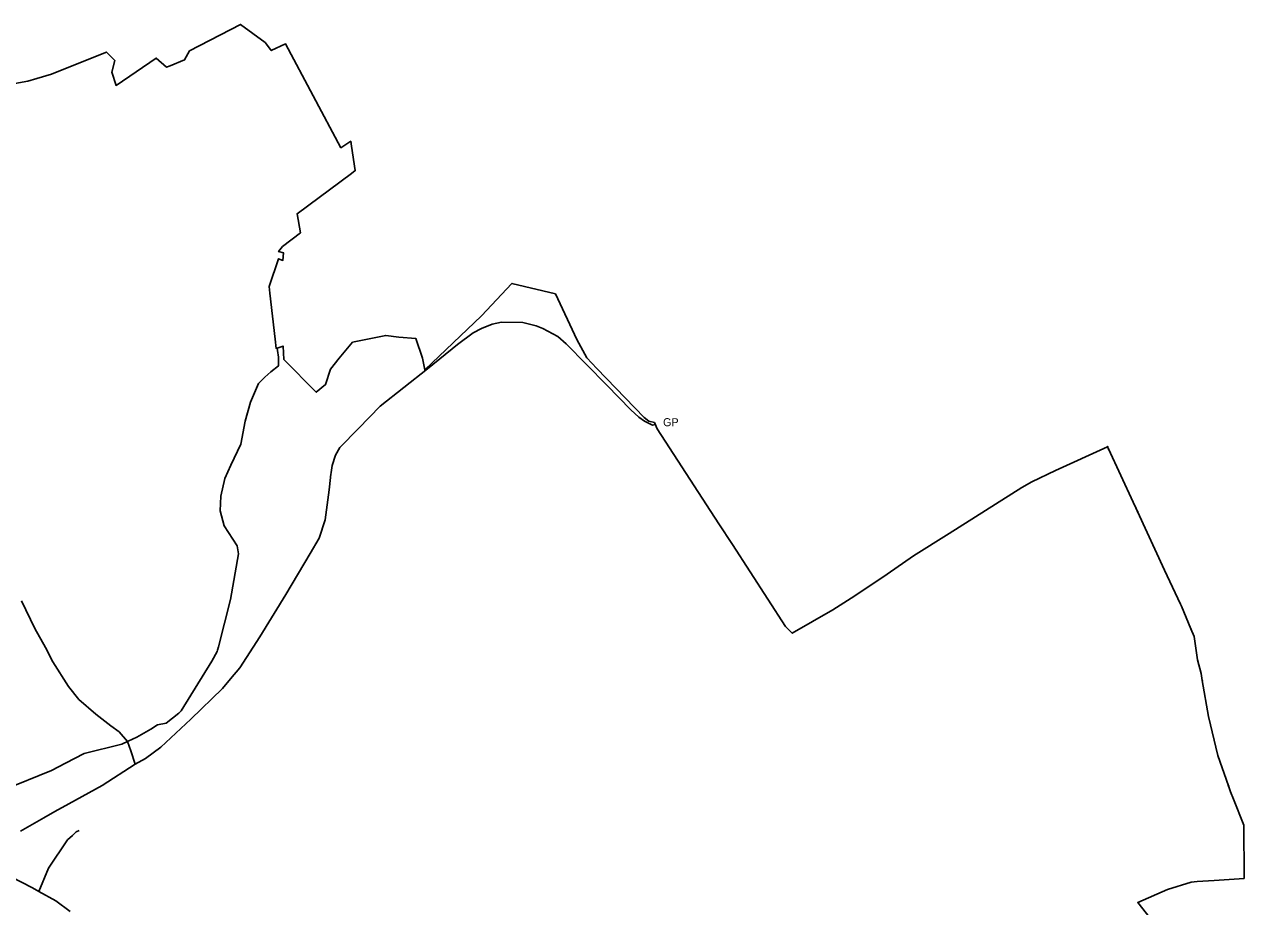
# Model space of a CAD drawing. Extents: x -617038 to -609441, y -1109294 to -1104285.
# Drawn here: x -612071 to -610546, y -1107289 to -1106187 of the extents above; entities that cross this region are included whole.
import ezdxf

# ---------------------------------------------------------------- set-up
doc = ezdxf.new("R2010")
doc.units = 0
for name, color, linetype in [('BOD_SET', 7, 'Continuous'), ('CESTY', 7, 'Continuous'), ('OVNE_PRE', 7, 'Continuous'), ('OVNE_SET', 7, 'Continuous'), ('VODA', 7, 'Continuous')]:
    doc.layers.add(name, color=color, linetype=linetype)

msp = doc.modelspace()

# ---------------------------------------------------------------- linework, layer by layer
at = {"layer": 'BOD_SET'}
for p, q in [((-610717.9, -1106714.2), (-610716.9, -1106715.2)), ((-610717.9, -1106715.2), (-610716.9, -1106714.2)), ((-610716.6, -1106717), (-610715.6, -1106718)), ((-610716.6, -1106718), (-610715.6, -1106717)), ((-610686, -1106783.4), (-610685, -1106784.4)), ((-610686, -1106784.4), (-610685, -1106783.4)), ((-610682.3, -1106791.4), (-610681.3, -1106792.4)), ((-610682.3, -1106792.4), (-610681.3, -1106791.4)), ((-610680.6, -1106795), (-610679.6, -1106796)), ((-610680.6, -1106796), (-610679.6, -1106795)), ((-610626.8, -1106910.8), (-610625.8, -1106911.8)), ((-610626.8, -1106911.8), (-610625.8, -1106910.8)), ((-610613.7, -1106941.8), (-610612.7, -1106942.8)), ((-610613.7, -1106942.8), (-610612.7, -1106941.8)), ((-610599.5, -1107006.1), (-610598.5, -1107007.1)), ((-610599.5, -1107007.1), (-610598.5, -1107006.1)), ((-610566.8, -1107138), (-610565.8, -1107139)), ((-610566.8, -1107139), (-610565.8, -1107138)), ((-610560.6, -1107154.4), (-610559.6, -1107155.4)), ((-610560.6, -1107155.4), (-610559.6, -1107154.4)), ((-610547.2, -1107251.9), (-610546.2, -1107252.9)), ((-610547.2, -1107252.9), (-610546.2, -1107251.9))]:
    msp.add_line(p, q, dxfattribs=at)
at = {"layer": 'CESTY'}
for points in [[(-612075.8, -1107195.1), (-612046.5, -1107178.3), (-612033, -1107170.5), (-612015.4, -1107161), (-611973.7, -1107138), (-611932.5, -1107111.4), (-611919.4, -1107104.3), (-611900.6, -1107089.9), (-611863.1, -1107055.1), (-611823.4, -1107016.9), (-611813.3, -1107004.8), (-611801.6, -1106990.8), (-611776.6, -1106952.3), (-611744.4, -1106899.3), (-611713.9, -1106848.3), (-611702.7, -1106829), (-611695.1, -1106805.9), (-611690, -1106768.6), (-611688.3, -1106753), (-611688.2, -1106752.3), (-611687.3, -1106744), (-611686.4, -1106738), (-611682.2, -1106725.1), (-611676.9, -1106715.6), (-611653.6, -1106692.1), (-611626.5, -1106663.9), (-611567.1, -1106617.3), (-611529.9, -1106587.2), (-611510.2, -1106572.6), (-611499.7, -1106566.9), (-611486.3, -1106561.6), (-611474.7, -1106559.3), (-611448, -1106559.6), (-611431.6, -1106563.5), (-611423.2, -1106566.9), (-611404.5, -1106577.1), (-611394, -1106586.2), (-611343, -1106637.7), (-611312.9, -1106668.6), (-611303.1, -1106677.9), (-611296.2, -1106682.8), (-611292.8, -1106684.3), (-611286, -1106687.6), (-611282.7, -1106687.1)], [(-611932.5, -1107111.4), (-611937.7, -1107094.8), (-611942, -1107082.9), (-611952.6, -1107070.8), (-611962.8, -1107063.2), (-611981.8, -1107048.8), (-612003, -1107030.4), (-612015.9, -1107014.1), (-612035.3, -1106983.5), (-612044.5, -1106965.5), (-612057.7, -1106941.7), (-612074.6, -1106907.4)]]:
    msp.add_lwpolyline(points, dxfattribs=at)
at = {"layer": 'OVNE_PRE'}
for points in [[(-610646.3, -1106868.9), (-610680.1, -1106795.5), (-610681.8, -1106791.9), (-610685.5, -1106783.9), (-610716.1, -1106717.5), (-610717.4, -1106714.8)], [(-610613, -1107258.5), (-610605.4, -1107258), (-610584.2, -1107256.6), (-610546.7, -1107254), (-610546.7, -1107252.4), (-610547, -1107187.3), (-610560.1, -1107154.9), (-610563.8, -1107145.7), (-610566.3, -1107138.5), (-610579.8, -1107100.3), (-610591.3, -1107051.8), (-610599, -1107006.6), (-610600.4, -1106998.1), (-610605.2, -1106980.9), (-610609.1, -1106951.8), (-610613.2, -1106942.3), (-610625.2, -1106913.9), (-610626.3, -1106911.3), (-610646.3, -1106868.9)], [(-610574.7, -1107411.6), (-610598.8, -1107383.5), (-610617.5, -1107361.1), (-610646.3, -1107326.4), (-610647.2, -1107325.3), (-610679.7, -1107284.3), (-610642.7, -1107268), (-610613, -1107258.5)]]:
    msp.add_lwpolyline(points, dxfattribs=at)
at = {"layer": 'OVNE_SET'}
for points in [[(-611283.7, -1106684.6), (-611290.6, -1106682.9), (-611296.4, -1106678.4), (-611355.7, -1106617.1), (-611368.1, -1106603.6), (-611380.6, -1106580.9), (-611407.4, -1106523.9), (-611461.7, -1106510.7), (-611499.7, -1106551.2), (-611570.7, -1106618.7), (-611573.4, -1106604.2), (-611581.9, -1106579.5), (-611603, -1106578), (-611619.4, -1106575.7), (-611660.7, -1106583.9), (-611677.7, -1106604), (-611688.4, -1106617.8), (-611694.8, -1106637), (-611706.3, -1106646.6), (-611746.9, -1106605.6), (-611747.6, -1106589), (-611756.4, -1106591.8), (-611757.5, -1106580.4), (-611764, -1106523), (-611765, -1106514.6), (-611753.4, -1106479.9), (-611747.8, -1106482), (-611747.1, -1106472.5), (-611753.2, -1106471), (-611748.3, -1106464.4), (-611725.9, -1106447.4), (-611730.2, -1106423.6), (-611662.2, -1106373.2), (-611657.5, -1106369.7), (-611662.1, -1106339.1), (-611663, -1106333), (-611675.3, -1106341.2), (-611744.7, -1106211.3), (-611762.5, -1106219.9), (-611764.7, -1106217), (-611770.1, -1106209.9), (-611801, -1106187.1), (-611864.7, -1106220.3), (-611870.8, -1106231.3), (-611888.8, -1106238.7), (-611893.2, -1106240.5), (-611906.2, -1106229.3), (-611956.3, -1106263.4), (-611961.7, -1106246.7), (-611957.7, -1106232.4), (-611968.3, -1106221.7), (-611996.6, -1106233.1), (-612036.9, -1106249.3), (-612055.4, -1106254.8), (-612066.7, -1106258), (-612131.6, -1106269.8)], [(-610717.4, -1106714.8), (-610782.5, -1106744.4), (-610812.1, -1106758.4), (-610824.5, -1106765.8), (-610915.2, -1106823), (-610959.7, -1106851), (-610992.7, -1106873.8), (-611033.1, -1106900.9), (-611060.5, -1106918.4), (-611111.4, -1106947.8), (-611119.7, -1106939.2), (-611186.2, -1106837), (-611203.2, -1106810.9), (-611280.3, -1106692.4), (-611283.7, -1106684.6)]]:
    msp.add_lwpolyline(points, dxfattribs=at)
at = {"layer": 'VODA'}
for points in [[(-611754.9, -1106591.2), (-611754.7, -1106594.5), (-611753.5, -1106602.7), (-611753.5, -1106613.7), (-611763.1, -1106621.1), (-611770.6, -1106628), (-611778.5, -1106635.8), (-611788.2, -1106658.9), (-611795, -1106682.9), (-611800.4, -1106711.7), (-611812.8, -1106737.7), (-611820.3, -1106754.4), (-611825.5, -1106776.4), (-611826.4, -1106794.8), (-611821.1, -1106813.5), (-611805, -1106838.7), (-611803.3, -1106848.5), (-611813.5, -1106905.6), (-611828.4, -1106964.9), (-611829.6, -1106968.9), (-611830.1, -1106970.6), (-611836.8, -1106982.5), (-611874.9, -1107044.5), (-611878, -1107047.5), (-611893.8, -1107060), (-611904.4, -1107062.3), (-611912.7, -1107067.4), (-611930.6, -1107077.4), (-611941.3, -1107082.6), (-611949.1, -1107086.1), (-611996.2, -1107097.9), (-612019.4, -1107109.9), (-612037, -1107119), (-612096.7, -1107143.5)], [(-612013.7, -1107295.2), (-612031.8, -1107282.1), (-612053, -1107270.2), (-612040.7, -1107241.4), (-612016.9, -1107205.8), (-612010.7, -1107200.2), (-612006.5, -1107196.2), (-612006, -1107195.9), (-612002.4, -1107194.2)], [(-612053, -1107270.2), (-612060.8, -1107265.9), (-612088.2, -1107251.8), (-612095.3, -1107245.8), (-612112.7, -1107253.1), (-612125.4, -1107252.7), (-612137.5, -1107250.6), (-612146.1, -1107251), (-612153.1, -1107254.4), (-612163.6, -1107261.1), (-612176, -1107268.7), (-612192.8, -1107273.5)]]:
    msp.add_lwpolyline(points, dxfattribs=at)

# ---------------------------------------------------------------- texts
at = {"layer": 'OVNE_SET'}
msp.add_text('GP', height=10, dxfattribs=at).set_placement((-611272.8, -1106689.1))

doc.saveas('drawing.dxf')
